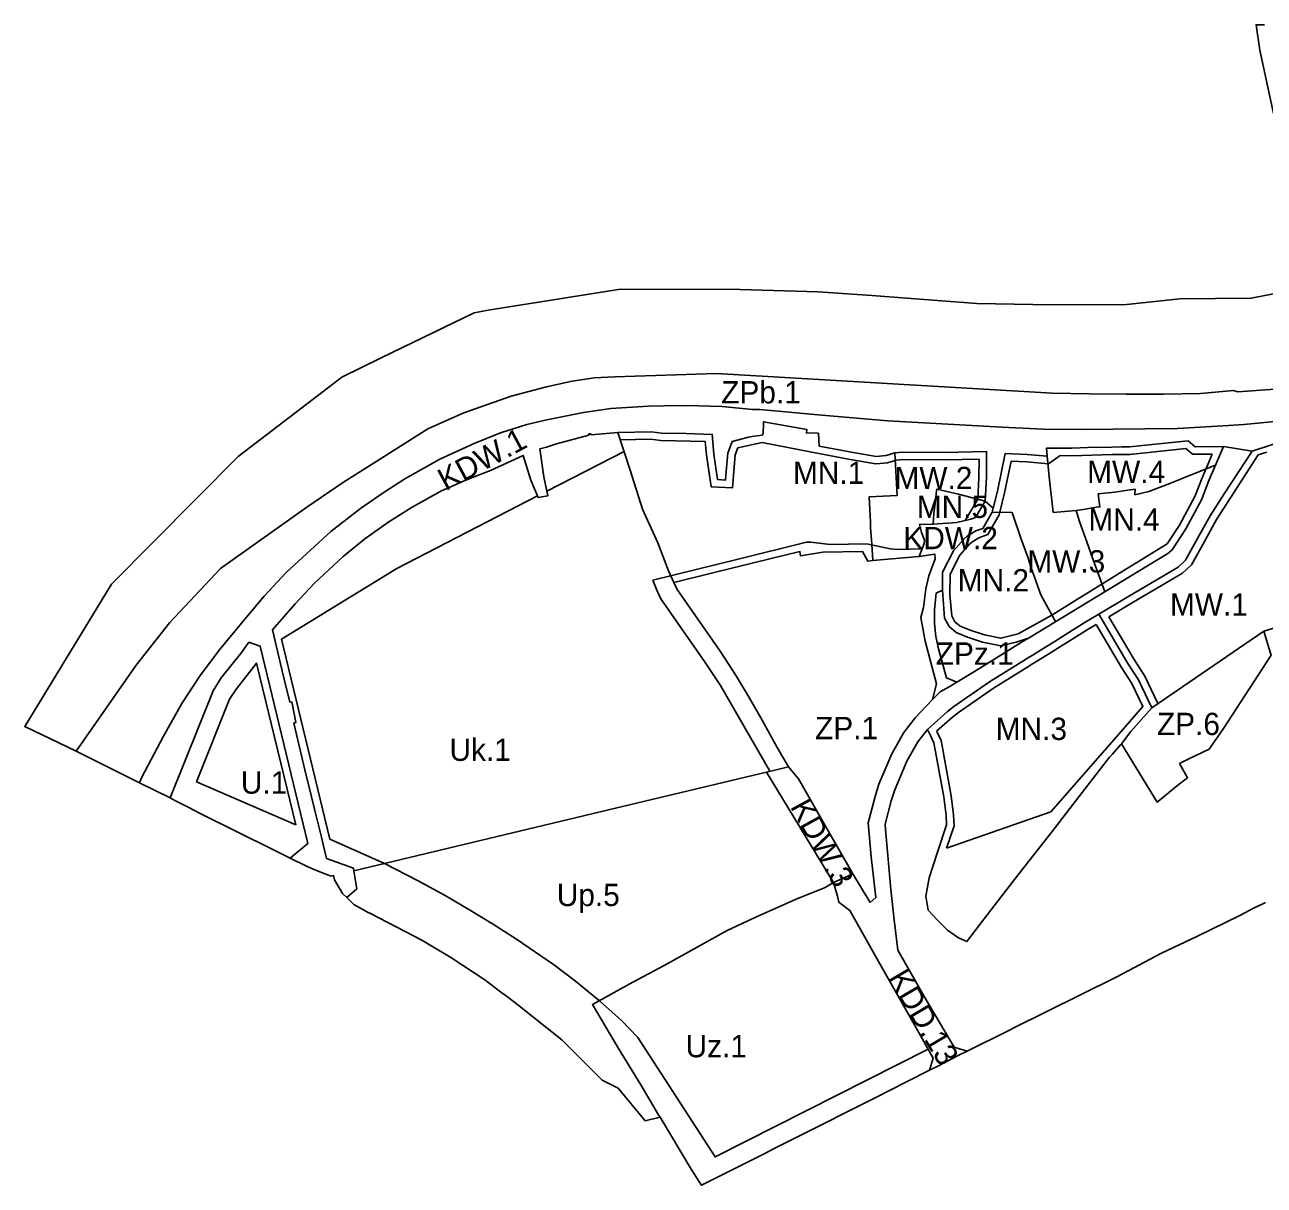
# Model space of a CAD drawing. Extents: x 7421697 to 7426767, y 5545731 to 5547485.
# Drawn here: x 7421697 to 7422364, y 5546202 to 5546826 of the extents above; entities that cross this region are included whole.
import ezdxf

# ---------------------------------------------------------------- set-up
doc = ezdxf.new("R2010")
doc.units = 0
for name, color, linetype in [('LIN_Linia Zabudowy Nieprzekraczalna', 7, 'Continuous'), ('LIN_linie_rozgraniczajace', 7, 'Continuous'), ('TXT_oznaczenia_przeznaczen', 7, 'Continuous')]:
    doc.layers.add(name, color=color, linetype=linetype)

msp = doc.modelspace()

# ---------------------------------------------------------------- linework, layer by layer
at = {"layer": 'LIN_Linia Zabudowy Nieprzekraczalna'}
for p, q in [((7421789.55, 5546418.73), (7421842.9, 5546395.53)), ((7422192.88, 5546383.08), (7422248.96, 5546402.64))]:
    msp.add_line(p, q, dxfattribs=at)
for points in [[(7422210.31, 5546592.34), (7422191.77, 5546591.97), (7422169.26, 5546592.14), (7422165.8, 5546591.7), (7422161.13, 5546590.31), (7422154.79, 5546589.78), (7422140.97, 5546592.18), (7422120.39, 5546596.03), (7422093.77, 5546601.2), (7422080.57, 5546598.41), (7422079.12, 5546594.56), (7422077.65, 5546576.82), (7422066.26, 5546577.5), (7422063.68, 5546594.59), (7422063.1, 5546601.73), (7422039.22, 5546602.34), (7422033.9, 5546603.07), (7422017.4, 5546602.73)], [(7422019.42, 5546596.52), (7421977.91, 5546575.12)], [(7422227.64, 5546591.23), (7422224.04, 5546574.16), (7422221.52, 5546563.76), (7422221.17, 5546562.36), (7422215.08, 5546551.75), (7422210.24, 5546550.04), (7422206.35, 5546547.75), (7422204.97, 5546546.43), (7422199.99, 5546540.72), (7422194.73, 5546530.51), (7422194.52, 5546519.3), (7422195.69, 5546507.98), (7422197.37, 5546504.88), (7422200.11, 5546502.48), (7422205.45, 5546500.29), (7422213.19, 5546497.73), (7422222.03, 5546496.01), (7422229.26, 5546497.73), (7422231.29, 5546498.41), (7422249.38, 5546508.41), (7422261.81, 5546516.06), (7422275.35, 5546524.46), (7422291.92, 5546534.73), (7422295.96, 5546537.22), (7422311.42, 5546546.8), (7422318.1, 5546556.84), (7422326.45, 5546572.54), (7422329.87, 5546581.41), (7422333.85, 5546590.69), (7422335.73, 5546595.07)], [(7422335.73, 5546595.07), (7422325.01, 5546594.92), (7422321.47, 5546598.07), (7422291.45, 5546594.86), (7422281.8, 5546594.8), (7422260.2, 5546594.19), (7422254.01, 5546594.29), (7422247.63, 5546589.87), (7422236, 5546590.84), (7422227.64, 5546591.23)], [(7422360.46, 5546594.59), (7422345.54, 5546571.43), (7422338, 5546559.83), (7422331.5, 5546548.02), (7422324.46, 5546535.48), (7422319.71, 5546531.04), (7422307.51, 5546523.79), (7422293.24, 5546515.32), (7422280.15, 5546507.57)], [(7422360.46, 5546594.59), (7422365.03, 5546596.05)], [(7422202.78, 5546559.34), (7422209.6, 5546570.73), (7422210.25, 5546582.49), (7422210.31, 5546592.34)], [(7421972.85, 5546572.51), (7421897.15, 5546533.47), (7421835.19, 5546495.48)], [(7422034.95, 5546527.19), (7422080.06, 5546538.4), (7422117.58, 5546547.71), (7422119.87, 5546547.68), (7422130.26, 5546546.44), (7422150.01, 5546546.69), (7422153.86, 5546545.88), (7422156.66, 5546545.36), (7422162.64, 5546544.04), (7422166.42, 5546543.78), (7422179.78, 5546544.1)], [(7422097.61, 5546424.75), (7422084.97, 5546446.89), (7422077.43, 5546459.92), (7422071.23, 5546470.55), (7422062.75, 5546483.45), (7422039.27, 5546517.24), (7422037.1, 5546521.87), (7422034.95, 5546527.19)], [(7422273.29, 5546503.44), (7422268.98, 5546500.79), (7422259.25, 5546494.79), (7422252.74, 5546490.72), (7422247.24, 5546487.26), (7422240.92, 5546483.32), (7422238.19, 5546481.64), (7422237.35, 5546481.12), (7422218.16, 5546469.21), (7422199.19, 5546455.97), (7422195.99, 5546453.45), (7422187.46, 5546445.91)], [(7422281.65, 5546440.01), (7422298.41, 5546459.18), (7422292.54, 5546471.69), (7422286.9, 5546480.23), (7422273.29, 5546503.44)], [(7422280.15, 5546507.57), (7422293.69, 5546484.47), (7422299.54, 5546475.62), (7422306.49, 5546460.8)], [(7421835.19, 5546495.48), (7421861.19, 5546387.96), (7421890.58, 5546374.8)], [(7421842.9, 5546395.53), (7421821.85, 5546482.59), (7421810.99, 5546468.81), (7421807.31, 5546463.12), (7421789.55, 5546418.73)], [(7422187.55, 5546445.72), (7422189.91, 5546440.91), (7422195.35, 5546411.19), (7422196.63, 5546400.98), (7422196.85, 5546395.04), (7422192.88, 5546383.08)], [(7422248.96, 5546402.64), (7422281.65, 5546440.01)], [(7421890.58, 5546374.8), (7421908.76, 5546365.49), (7421923.17, 5546357.55), (7421936.84, 5546349.59), (7421948.6, 5546342.43), (7421961.55, 5546334.1), (7421981.44, 5546320.38), (7421993.33, 5546311.47), (7422002.28, 5546304.23), (7422006.22, 5546300.97)], [(7422006.22, 5546300.92), (7422018.11, 5546290.4), (7422026.76, 5546281.19), (7422068.35, 5546216.95), (7422182.96, 5546275)]]:
    msp.add_lwpolyline(points, dxfattribs=at)
at = {"layer": 'LIN_linie_rozgraniczajace'}
for p, q in [((7422213.54, 5546569.66), (7422217.96, 5546566.04)), ((7422274.68, 5546508.98), (7422290.29, 5546482.35)), ((7422363.49, 5546499.79), (7422303.14, 5546458.51)), ((7422318.13, 5546428.57), (7422322.79, 5546430.84)), ((7422131.98, 5546364.54), (7422096.03, 5546424)), ((7421849.44, 5546385.53), (7421839.81, 5546377.67))]:
    msp.add_line(p, q, dxfattribs=at)
for points in [[(7422368.67, 5546778.27), (7422361.35, 5546812.29), (7422359.29, 5546825.98), (7422363.8, 5546825.99)], [(7422364.42, 5546353.84), (7422362.57, 5546352.95), (7422358.29, 5546350.92), (7422350.46, 5546346.9), (7422327.71, 5546335.76), (7422308.36, 5546326.55), (7422284.33, 5546313.85), (7422264.44, 5546304.04), (7422228.99, 5546286.31), (7422226.41, 5546285.02), (7422203.88, 5546273.84), (7422199.4, 5546271.62), (7422188.19, 5546265.8), (7422183.72, 5546263.57), (7422171.63, 5546257.52), (7422153.67, 5546248.42), (7422141.5, 5546242.29), (7422123.73, 5546233.33), (7422110.21, 5546226.46), (7422100.91, 5546221.78), (7422094.69, 5546218.65), (7422081.2, 5546211.88), (7422060.98, 5546201.73), (7422059.59, 5546203.96), (7422055.59, 5546210.35), (7422038.75, 5546238.26), (7422030.72, 5546236.4), (7422016.3, 5546253.86), (7422007.61, 5546258.22), (7421986.05, 5546279.86), (7421962.32, 5546298.82), (7421955.23, 5546304.15), (7421953.96, 5546305.1), (7421944.53, 5546312.18), (7421926.27, 5546324.19), (7421910.7, 5546333.57), (7421883.09, 5546347.86), (7421881.8, 5546348.53), (7421874.17, 5546352.77), (7421870.29, 5546356.54), (7421868.11, 5546358.65), (7421863.73, 5546366.03), (7421863.27, 5546368.26), (7421861.85, 5546367.92), (7421857.57, 5546369.64), (7421852.81, 5546371.56), (7421848.98, 5546373.11), (7421839.81, 5546377.67), (7421831.22, 5546381.93), (7421791.91, 5546401.46), (7421784.72, 5546405.21), (7421777.9, 5546408.76), (7421775.3, 5546410.06), (7421758.81, 5546418.26), (7421724.76, 5546435.2), (7421697.18, 5546448.43), (7421743.76, 5546525.03), (7421811.88, 5546593.74), (7421860.64, 5546631.05), (7421867.69, 5546636.44), (7421888.88, 5546646.91), (7421938.87, 5546671.01), (7421946.29, 5546672.42), (7422017.49, 5546683.75), (7422081.74, 5546683.56), (7422123.83, 5546682.26), (7422152.63, 5546680.43), (7422209.04, 5546676.11), (7422239.19, 5546675.54), (7422287.94, 5546675.31), (7422318.19, 5546678.64), (7422356.71, 5546678.9), (7422374.12, 5546682.31)], [(7422347.08, 5546629.23), (7422349.4, 5546628.48), (7422369.29, 5546630), (7422389.04, 5546631.99), (7422588.25, 5546665.06), (7422640.88, 5546674.26)], [(7421724.76, 5546435.2), (7421757.08, 5546481.42), (7421775.06, 5546504.33), (7421802.41, 5546533.58), (7421848.77, 5546566.51), (7421868.59, 5546580), (7421881.07, 5546587.74), (7421913.9, 5546608.67), (7421933.28, 5546617.2), (7421958.69, 5546626.23), (7421977.8, 5546631.3), (7421991.58, 5546634.23), (7422003.38, 5546636.14), (7422014.45, 5546636.57), (7422069.2, 5546638.32), (7422249.64, 5546627.83), (7422269.5, 5546627.39), (7422289.48, 5546627.23), (7422309.48, 5546627.3), (7422329.45, 5546627.68), (7422347.08, 5546629.23)], [(7421977.84, 5546613.43), (7421997.63, 5546617.46), (7422012.32, 5546619.51), (7422032.48, 5546620.84), (7422041, 5546620.99), (7422053.4, 5546621.16), (7422072.18, 5546620.59), (7422088.55, 5546619.11), (7422092.42, 5546618.99), (7422125.8, 5546615.93)], [(7422125.8, 5546615.93), (7422161.21, 5546612.91), (7422222.53, 5546609.44), (7422245, 5546608.38), (7422265.11, 5546608.23), (7422317.01, 5546608.88), (7422344.52, 5546610.36), (7422352.71, 5546611.01), (7422384.46, 5546613.98)], [(7421758.81, 5546418.26), (7421760.2, 5546421.27), (7421771.72, 5546443.35), (7421781.69, 5546460.8), (7421791.16, 5546475.43), (7421801.62, 5546489.6), (7421814.53, 5546505.25), (7421825.92, 5546518.53), (7421837.7, 5546531.34), (7421861.83, 5546553.42), (7421877.68, 5546565.71), (7421889.86, 5546574.24), (7421901.52, 5546581.66), (7421920.36, 5546592.28), (7421938.84, 5546600.73), (7421952.99, 5546606.53), (7421967.12, 5546610.95), (7421977.84, 5546613.43)], [(7421830.41, 5546500.49), (7421842.59, 5546514.57), (7421852.97, 5546525.68), (7421868.32, 5546539.88), (7421879.95, 5546549.38), (7421892.91, 5546558.61), (7421905.57, 5546566.46), (7421921.26, 5546575.23), (7421934.77, 5546581.12), (7421947.6, 5546586.15), (7421965.18, 5546594.33), (7421969.34, 5546580.98), (7421973.21, 5546571.64), (7421978.43, 5546572.58), (7421976.33, 5546582.88), (7421974.21, 5546597.89), (7421977.67, 5546598.76), (7421983.15, 5546600.52), (7422000.47, 5546605.26), (7422000.42, 5546605.93), (7422001.52, 5546605.87), (7422001.76, 5546605.48), (7422016.1, 5546606.71), (7422034.13, 5546607.07), (7422039.54, 5546606.34), (7422052.88, 5546606.18), (7422066.8, 5546605.64), (7422067.65, 5546595.05), (7422069.73, 5546581.3), (7422073.99, 5546581.04), (7422074.26, 5546585.7), (7422075.18, 5546595.45), (7422077.6, 5546601.87), (7422086.41, 5546604.13), (7422089.4, 5546604.61), (7422092.39, 5546605.09), (7422094.04, 5546605.36), (7422094.14, 5546606.74), (7422094.24, 5546608.12), (7422094.35, 5546609.55), (7422094.46, 5546610.99), (7422094.48, 5546612.41), (7422117.7, 5546608.3), (7422117.44, 5546606.47), (7422123.96, 5546606.24), (7422124.25, 5546599.38), (7422141.68, 5546596.12), (7422154.97, 5546593.81), (7422160.39, 5546594.26), (7422164.97, 5546595.63), (7422169.02, 5546596.14), (7422191.74, 5546595.97), (7422214.34, 5546596.42), (7422214.25, 5546582.36), (7422213.54, 5546569.66)], [(7422142.42, 5546369.27), (7422127.81, 5546394.81), (7422113.2, 5546420.36), (7422107.79, 5546426.82), (7422101.78, 5546437.29), (7422093.65, 5546451.85), (7422086.07, 5546464.94), (7422079.74, 5546475.82), (7422071.03, 5546489.05), (7422047.97, 5546522.25), (7422046.27, 5546525.88), (7422043.33, 5546532.16), (7422037.56, 5546547.34), (7422029.35, 5546565.39), (7422022.74, 5546586.34), (7422016.1, 5546606.71)], [(7422217.96, 5546566.04), (7422220.14, 5546575.05), (7422224.43, 5546595.38), (7422236.26, 5546594.84), (7422246.89, 5546593.94), (7422246.61, 5546598.16), (7422260.14, 5546598.19), (7422268.57, 5546598.52), (7422281.73, 5546598.8), (7422287.27, 5546598.92), (7422287.82, 5546598.91), (7422288.36, 5546598.9), (7422289.79, 5546598.88), (7422291.22, 5546598.86), (7422322.81, 5546602.23), (7422326.5, 5546598.94), (7422341.84, 5546599.16)], [(7422357.16, 5546596.69), (7422368.06, 5546600.16), (7422368.33, 5546600.22), (7422372.39, 5546600.92), (7422373.74, 5546601.23)], [(7422341.84, 5546599.16), (7422337.52, 5546589.12), (7422333.57, 5546579.9), (7422330.09, 5546570.87), (7422321.54, 5546554.79), (7422314.08, 5546543.57), (7422311.86, 5546541.49), (7422300.83, 5546534.94), (7422236.81, 5546496.03), (7422234.11, 5546494.39), (7422211, 5546480.07), (7422198.36, 5546472.43), (7422194.19, 5546469.92), (7422189.36, 5546467.22), (7422185.3, 5546462.95), (7422175.95, 5546453.1), (7422169.94, 5546445.31), (7422163.41, 5546433.88), (7422156.48, 5546417.49), (7422154.46, 5546410.93), (7422150.77, 5546396.66), (7422152.24, 5546378.38), (7422154.82, 5546356.47), (7422151.76, 5546353.77)], [(7422196.86, 5546275.93), (7422181.28, 5546302.28), (7422166.63, 5546328.25), (7422164.61, 5546344.49), (7422162.86, 5546360.75), (7422161.21, 5546379.15), (7422160.09, 5546393.01), (7422159.86, 5546395.87), (7422163.12, 5546408.48), (7422164.94, 5546414.4), (7422171.49, 5546429.88), (7422177.44, 5546440.3), (7422182.52, 5546446.88), (7422193.43, 5546456.52), (7422196.81, 5546459.18), (7422215.95, 5546472.55), (7422235.24, 5546484.52), (7422236.09, 5546485.04), (7422238.82, 5546486.72), (7422245.11, 5546490.65), (7422250.62, 5546494.11), (7422257.14, 5546498.19), (7422266.88, 5546504.2), (7422274.68, 5546508.98), (7422291.2, 5546518.76), (7422305.47, 5546527.23), (7422317.29, 5546534.25), (7422321.27, 5546537.98), (7422328, 5546549.96), (7422334.56, 5546561.89), (7422342.18, 5546573.6), (7422349.6, 5546585.12), (7422357.16, 5546596.69), (7422341.84, 5546599.16)], [(7422164.97, 5546595.63), (7422166.2, 5546572.85)], [(7422250.11, 5546563.71), (7422249.43, 5546570.02), (7422248.75, 5546576.33), (7422248.41, 5546579.56), (7422248.06, 5546582.79), (7422247.48, 5546588.37), (7422246.89, 5546593.94)], [(7422294.22, 5546576.14), (7422294.14, 5546573.2), (7422301.59, 5546574.85), (7422312.92, 5546579.25), (7422325.22, 5546584.18), (7422337.52, 5546589.12)], [(7422187.25, 5546574.16), (7422187.62, 5546576.19), (7422199.28, 5546573.5), (7422213.54, 5546569.66)], [(7422262.61, 5546564.73), (7422267.62, 5546565.5), (7422271.2, 5546566.05), (7422274.77, 5546566.61), (7422275.26, 5546566.65), (7422274.33, 5546573.61), (7422283.36, 5546574.58), (7422290.26, 5546575.65), (7422294.22, 5546576.14)], [(7422166.2, 5546572.85), (7422151.23, 5546572.07), (7422151.55, 5546565.28), (7422151.88, 5546558.48), (7422152, 5546555.48), (7422152.59, 5546546.61), (7422153.17, 5546537.75)], [(7422181.29, 5546494.43), (7422179.06, 5546507.13), (7422180.36, 5546512.44), (7422181.62, 5546522.51), (7422183.34, 5546529.56), (7422186.7, 5546538.73), (7422186.58, 5546541.13), (7422178.17, 5546539.95), (7422180.88, 5546546.94), (7422180.91, 5546548.66), (7422179.39, 5546552.89), (7422178.24, 5546557.16), (7422185.67, 5546557.32), (7422198.42, 5546558.3), (7422205.89, 5546560.08), (7422208.33, 5546560.86), (7422213.54, 5546569.66)], [(7422187.25, 5546574.16), (7422187.06, 5546571.33), (7422186.04, 5546563.17), (7422185.67, 5546557.32)], [(7422217.96, 5546566.04), (7422217.42, 5546563.87), (7422212.35, 5546555.02), (7422208.55, 5546553.68), (7422203.92, 5546550.96), (7422202.08, 5546549.19), (7422196.65, 5546542.98), (7422190.74, 5546531.51), (7422190.57, 5546521.81), (7422187.23, 5546520.16), (7422186.3, 5546511.21), (7422186.35, 5546503.96), (7422187.12, 5546496.95), (7422188.52, 5546490.34)], [(7422217.42, 5546563.87), (7422228.09, 5546563.59), (7422232.73, 5546549.8), (7422236.45, 5546539.56), (7422238.25, 5546533.83), (7422243.59, 5546519.39), (7422251.41, 5546504.9)], [(7422277.92, 5546521.01), (7422275.12, 5546528.79), (7422271.74, 5546538.22), (7422270.47, 5546541.79), (7422269.2, 5546545.35), (7422264.4, 5546558.82), (7422262.61, 5546564.73), (7422250.11, 5546563.71)], [(7422178.17, 5546539.95), (7422163.42, 5546538.72), (7422153.17, 5546537.75), (7422150.46, 5546537.39), (7422147.64, 5546542.65), (7422126.33, 5546542.3), (7422114.24, 5546540.31), (7422114.02, 5546542.71), (7422081.03, 5546534.51), (7422046.27, 5546525.88)], [(7422236.81, 5546496.03), (7422230.35, 5546493.88), (7422222.11, 5546491.92), (7422212.18, 5546493.85), (7422204.06, 5546496.53), (7422197.98, 5546499.03), (7422194.2, 5546502.35), (7422191.77, 5546506.81), (7422190.57, 5546521.81)], [(7422322.79, 5546430.84), (7422334.12, 5546436.39), (7422341.69, 5546447.48), (7422367.46, 5546486.8), (7422366.38, 5546490.34), (7422363.49, 5546499.79), (7422391.68, 5546508.35)], [(7421830.41, 5546500.49), (7421833.87, 5546485.93), (7421836.49, 5546474.62), (7421839.74, 5546461.52), (7421840.69, 5546461.68), (7421843.01, 5546450.57), (7421841.81, 5546450.23), (7421847.83, 5546425.14), (7421851.4, 5546410.71), (7421853.17, 5546403.38), (7421854.95, 5546396.05), (7421856.68, 5546388.99), (7421858.4, 5546381.94), (7421859.48, 5546377.57)], [(7421775.3, 5546410.06), (7421798.39, 5546467.73), (7421802.84, 5546474.63), (7421813.83, 5546488.57), (7421817.59, 5546493.9)], [(7421817.59, 5546493.9), (7421823.74, 5546491.77), (7421849.44, 5546385.53)], [(7422181.29, 5546494.43), (7422187.44, 5546471.4), (7422185.3, 5546462.95)], [(7422188.52, 5546490.34), (7422192.77, 5546474.68), (7422198.36, 5546472.43)], [(7422290.29, 5546482.35), (7422296.04, 5546473.66), (7422303.14, 5546458.51)], [(7422303.14, 5546458.51), (7422291.97, 5546445.74), (7422286.83, 5546439.21)], [(7422182.52, 5546446.88), (7422184.22, 5546443.62), (7422186.08, 5546439.64), (7422191.4, 5546410.58), (7422192.64, 5546400.66), (7422192.83, 5546395.62), (7422188.11, 5546381.42), (7422183.48, 5546367.13), (7422181.64, 5546357.24), (7422182.97, 5546349.78), (7422187.89, 5546344.35), (7422193.32, 5546339.01), (7422199.34, 5546334.8), (7422203.79, 5546332.78), (7422213.07, 5546345.03), (7422221.94, 5546356.71), (7422231.22, 5546368.6), (7422249.55, 5546391.95), (7422260.86, 5546406.79), (7422274.87, 5546424.74), (7422280.54, 5546432.03), (7422281.85, 5546433.52), (7422286.32, 5546438.59), (7422286.83, 5546439.21)], [(7422286.83, 5546439.21), (7422306.04, 5546407.88), (7422317.23, 5546416.98), (7422322.47, 5546420.95), (7422318.13, 5546428.57)], [(7421874.11, 5546370.86), (7422014.86, 5546404.56), (7422096.03, 5546424), (7422107.79, 5546426.82)], [(7421859.48, 5546377.57), (7421873.87, 5546372.34), (7421874.11, 5546370.86), (7421875.72, 5546361.16), (7421870.29, 5546356.54)], [(7422151.76, 5546353.77), (7422142.42, 5546369.27), (7422140.07, 5546368.17), (7422131.98, 5546364.54), (7422134.15, 5546357.18), (7422134.9, 5546353.99), (7422140.87, 5546349.54), (7422152.12, 5546329.46), (7422156.28, 5546322.01), (7422175.56, 5546288.04), (7422185.72, 5546270.15)], [(7422038.75, 5546238.26), (7422038.18, 5546239.24), (7422028.5, 5546255.8), (7422016.51, 5546275.21), (7422002.41, 5546298.86), (7422024.22, 5546310.92), (7422040.93, 5546319.98), (7422063.62, 5546332.55), (7422074.93, 5546338.82), (7422091.05, 5546346.25), (7422111.88, 5546355.57), (7422127.53, 5546361.82), (7422131.98, 5546364.54)], [(7422203.88, 5546273.84), (7422196.86, 5546275.93)], [(7422185.72, 5546270.15), (7422183.72, 5546263.57)]]:
    msp.add_lwpolyline(points, dxfattribs=at)

# ---------------------------------------------------------------- texts
at = {"layer": 'TXT_oznaczenia_przeznaczen'}
for s, p in [('ZPb.1', (7422071.66, 5546622.29)), ('MN.1', (7422110.25, 5546579.01)), ('MW.2', (7422164.82, 5546576.18)), ('MW.4', (7422268.46, 5546579.44)), ('MN.5', (7422176.83, 5546560.7)), ('MN.4', (7422269.1, 5546553.78)), ('KDW.2', (7422169.61, 5546543.89)), ('MW.3', (7422236.27, 5546531.33)), ('MN.2', (7422198.83, 5546521.15)), ('MW.1', (7422312.99, 5546508.14)), ('ZPz.1', (7422187.01, 5546481.73)), ('ZP.6', (7422305.96, 5546443.88)), ('ZP.1', (7422122.12, 5546441.68)), ('MN.3', (7422219.25, 5546441.23)), ('Uk.1', (7421925.55, 5546430.01)), ('U.1', (7421813.35, 5546412.35)), ('Up.5', (7421983.23, 5546351.88)), ('Uz.1', (7422052.5, 5546270.55))]:
    msp.add_text(s, height=12, dxfattribs=at).set_placement(p)
for s, rotation, p in [('KDW.1', 28.37097, (7421923.5, 5546574.97)), ('KDW.3', 298.81093, (7422108.5, 5546405.43)), ('KDD.13', 300.55827, (7422161.02, 5546313.37))]:
    msp.add_text(s, height=12, rotation=rotation, dxfattribs=at).set_placement(p)

doc.saveas('drawing.dxf')
